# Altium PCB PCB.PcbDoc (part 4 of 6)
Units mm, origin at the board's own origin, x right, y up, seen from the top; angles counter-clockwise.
Board outline 101.6 x 101.61 mm, 4 copper layers (Top Layer, GND, POWER, Bottom Layer), stack 1.371 mm thick; 506 components, 346 nets, 1798 pads, 1471 vias.
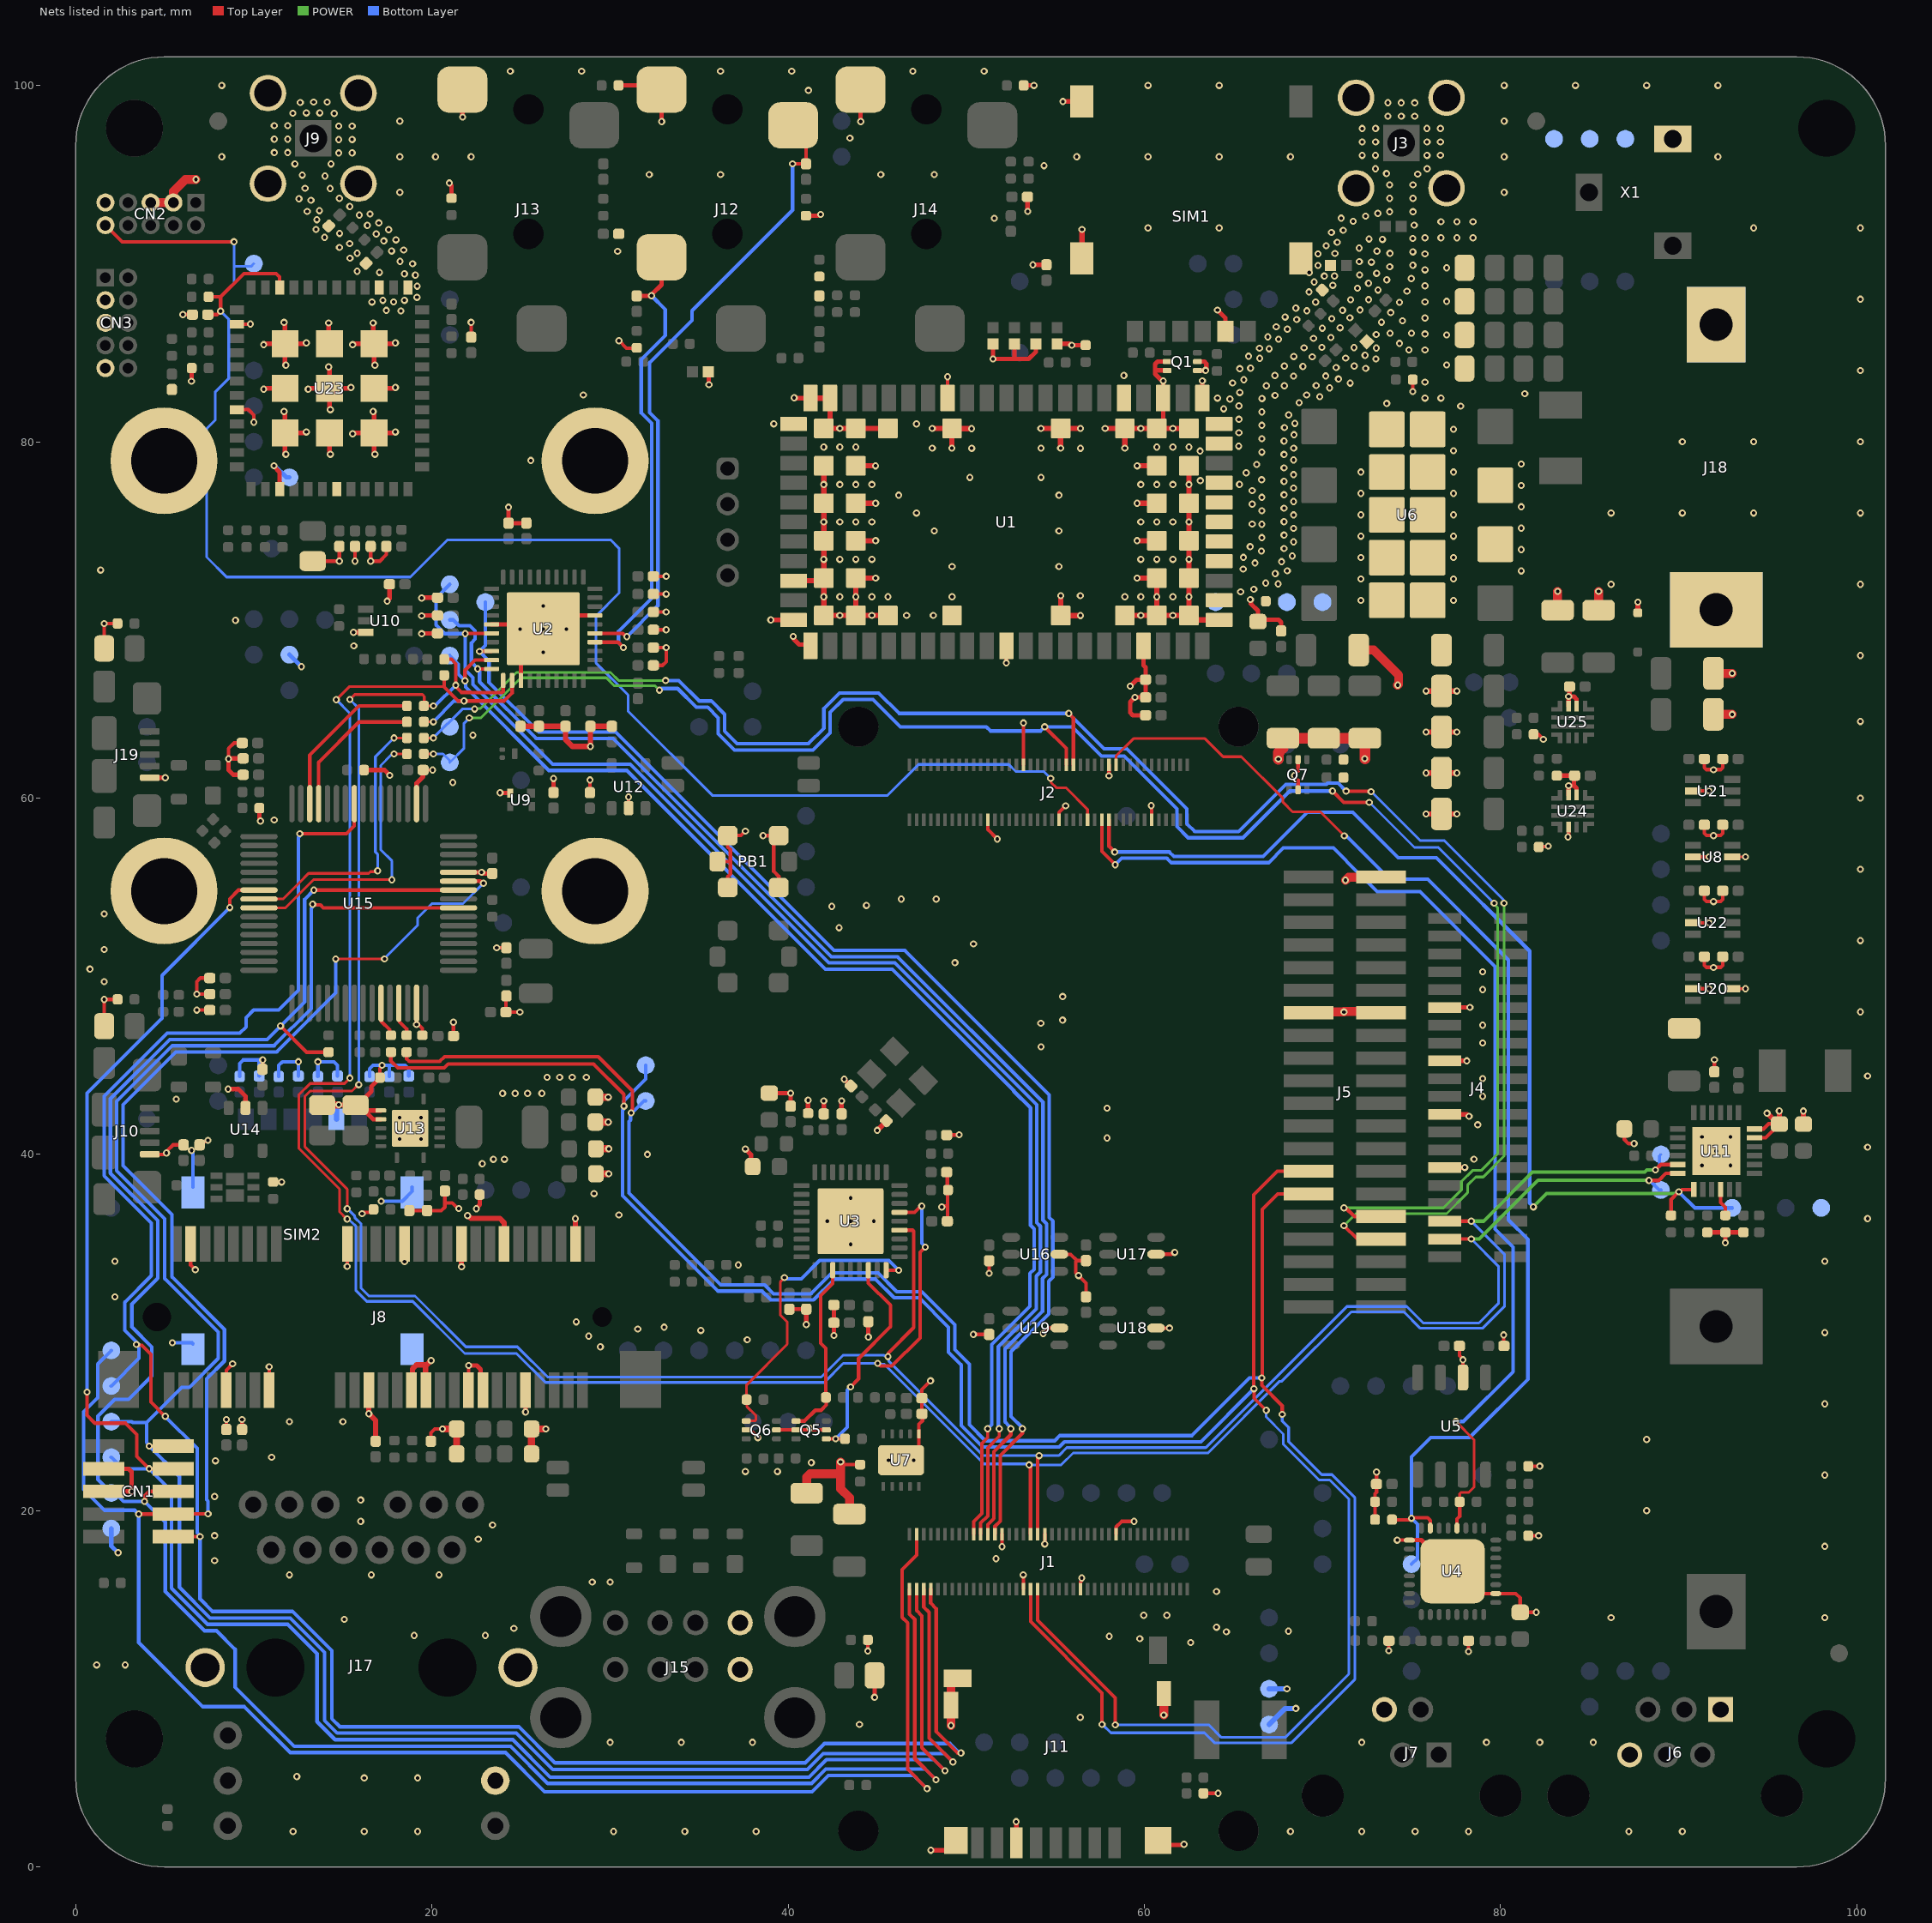
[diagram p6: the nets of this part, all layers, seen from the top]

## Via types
v1: diameter 0.4, hole 0.2, Top Layer to Bottom Layer, tented both sides, 1471 vias

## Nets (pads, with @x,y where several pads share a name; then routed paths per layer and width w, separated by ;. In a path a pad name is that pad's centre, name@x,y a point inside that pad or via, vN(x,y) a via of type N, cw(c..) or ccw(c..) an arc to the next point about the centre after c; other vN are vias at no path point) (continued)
FD_TX_TERM_1: J2.56 R46.1 U4.12 | length 62.1
  Top Layer w0.15: v1(77.479,25.01) 78.5,23.989 78.5,21.315 78.219,21.034 77.788,21.034 77.7,20.946 R46.1@77.7,20.5
  Top Layer w0.2: J2.56@57.61,58.785 57.61,57.009 v1(58.36,56.259) ; U4.12@77.55,19.025 77.55,19.529 77.7,19.679 R46.1@77.7,20.5
  Bottom Layer w0.2: v1(58.36,56.259) 58.726,56.625 61.258,56.625 61.509,56.374 66.974,56.374 67.8,57.2 70.611,57.2 72.09,55.721 73.061,54.751 75.478,54.751 79.69,50.539 79.69,35.805 80.7,34.795 80.7,27.8 77.91,25.01 v1(77.479,25.01)
GND: BAT_GND.X C1.1 C2.1 C3.1 C4.1 C5.1 C6.1 C7.2 C10.1 C11.1 C12.1 C13.1 C14.1 C15.1 C16.1 C17.1 C18.1 C19.1 C20.2 C21.2 C24.1 C25.1 C26.1 C27.1 C28.1 C29.1 C30.1 C32.2 C33.2 C34.1 C35.1 C36.1 C37.1 C39.1 C40.2 C43.1 C44.1 C45.2 C46.2 C48.2 C49.2 C50.2 C51.1 C52.2 C55.2 C56.2 C57.1 C58.2 C59.1 C60.1 C61.1 C62.1 C63.2 C64.1 C65.1 C66.1 C67.1 C68.1 C69.1 C70.1 C71.1 C72.1 C73.1 C74.1 C75.1 C76.1 C77.1 C78.1 C79.1 C80.1 C81.2 C82.1 C83.1 C85.1 C86.2 C87.1 C88.2 C89.1 C90.1 C91.1 C92.1 C94.1 C95.1 C96.1 C97.2 C98.1 C99.1 C100.1 C101.1 C102.1 C103.1 C104.1 C105.1 C106.1 C107.2 C108.1 C109.1 C110.1 C111.1 C112.2 C113.2 C114.2 C115.2 C117.1 C121.1 C122.1 C123.1 C124.1 C125.1 C126.1 C127.2 C129.1 C130.1 C131.1 C132.1 C133.1 C134.1 C135.1 C136.1 C137.1 C138.1 C139.1 C140.1 C141.1 C142.1 C143.1 C144.1 C145.1 C146.1 C147.1 C148.1 C149.1 C150.1 C151.1 C152.1 C153.1 C154.1 C155.1 C156.1 C157.1 C158.1 CN1.3 CN1.5 CN2.3 CN2.5 CN2.9 CN3.3 CN3.5 CN3.9 D1.A D2.A D3.A D4.A D9.A D10.1 D12.A D13.A D14.A D15.A D16.A DBG_GND.X GND_3V3_1.X GND_3V3_2.X GND_3V8_1.X GND_3V8_2.X GND_3V8_3.X H1.1 H2.1 H3.1 H4.1 J1.22 J1.31 J1.42 J1.47 J1.54 J2.24 J2.33 J2.44 J2.57 J2.70 J3.2 J3.3 J3.4 J3.5 J4.6 J4.9 J4.12 J4.15 J5.2 J5.13 J5.14 J6.1 J6.6 J7.4 J8.4 J8.9 J8.15 J8.18 J8.21 J8.26 J8.27 J8.29 J8.34 J8.35 J8.37 J8.40 J8.43 J8.50 J9.2 J9.3 J9.4 J9.5 J10.5 J11.6 J11.CD2 J11.SH1 J11.SH2 J11.SH3 J11.SH4 J12.1 J13.1 J14.1 J15.4 J15.8 J17.13 J17.SH1 J17.SH2 J18.1 J18.2 J19.5 JTAG_GND.X L1.1 LoRa_GND.X PB1.5 PB1.PAD PWR_GND1.X PWR_GND2.X PWR_GND3.X Q1.2 Q1.3 Q1.4 Q1.5 Q5.2 Q5.5 Q6.2 Q6.5 Q7.2 Q7.5 R3.1 R7.1 R17.1 R18.2 R24.1 R25.1 R26.1 R27.1 R28.1 R29.1 R49.2 R50.1 R52.1 R53.2 R55.2 R58.2 R59.1 R66.1 R67.1 R72.2 R74.1 R75.1 R77.1 R78.1 R79.1 R82.1 R84.1 R85.1 R87.2 R89.2 R117.2 R118.1 R121.1 R122.1 R124.1 R126.2 SIM1.C5 SIM1.G1 SIM1.G2 SIM1.G4 SIM2.C5 SIM2.G1 SIM2.G2 SIM2.G3 SIM2.G4 U1.1 U1.3 U1.5 U1.14 U1.20 U1.21 U1.22 U1.30 U1.32 U1.33 U1.43 U1.50 U1.54 U1.55 U1.57 U1.58 U1.59 U1.60 U1.61 U1.63 U1.64 U1.65 U1.66 U1.67 U1.68 U1.69 U1.70 U1.71 U1.72 U1.73 U1.74 U1.75 U1.76 U1.77 U1.78 U1.79 U1.80 U1.81 U1.82 U1.83 U1.84 U1.85 U1.86 U1.87 U1.88 U1.89 U1.90 U1.91 U1.92 U1.93 U1.94 U1.95 U1.96 U2.3 U2.17 U2.35 U2.41 U3.37 U4.2 U4.17 U4.33 U5.2 U6.GND U7.1 U7.11 U8.2 U8.5 U9.2 U10.3 U11.17 U11.18 U11.EXP U12.2 U13.2 U13.3 U13.15 U14.2 U15.12 U15.18 U15.63 U16.2 U17.2 U18.2 U19.2 U20.2 U20.5 U21.2 U22.2 U23.3 U23.7 U23.25 U23.27 U23.38 U23.44 U23.49 U23.50 U23.51 U23.52 U23.53 U23.54 U23.55 U23.56 U23.57 U24.2 U24.8 U24.9 U25.8 U25.9 X1.2 | length 448.4
  Top Layer w0.15: C99.1@19.505,61.575 v1@20.039,61.575 ; U20.5@93,49.3 v1(93.75,49.3) ; U8.5@93,56.7 v1(93.75,56.7)
  Top Layer w0.2: C157.1@1.6,47.2 v1(1.6,48.7) R84.1@2.35,48.7 ; C158.1@1.6,68.4 v1(1.6,69.8) R85.1@2.35,69.8 ; J10.5@4.16,40.01 4.169,40.001 4.962,40.001 5.043,40.083 v1(5.097,40.083) ; v1@5.135,40.06 5.135,40.205 5.465,40.535 C117.1@6.055,40.535 ; v1(6.014,87.138) C60.1@6.549,87.138 ; J8.4@6.457,34.977 6.453,34.973 6.453,33.791 6.713,33.531 v1(6.713,33.528) ; v1(6.8,48.1) C101.1@7.53,48.1 ; C96.1@6.955,40.535 7.139,40.719 7.296,40.719 7.371,40.794 v1(7.425,40.794) ; C109.1@7.53,49 v1(6.8,49) 6.8,49.7 7,49.9 C108.1@7.53,49.9 ; J8.9@8.457,26.777 8.457,27.885 8.809,28.237 v1(8.809,28.246) ; C20.2@8.459,24.558 v1(8.459,25.121) ; v1(8.581,62.203) 8.581,62.782 8.893,63.093 C110.1@9.35,63.093 ; U23.44@9.05,81.8 9.7,81.8 10,81.5 v1(10,81.1) ; U23.38@9.05,86.6 v1@9.8,86.6 ; C52.2@9.339,24.558 v1(9.339,25.121) ; C97.2@10.485,44.775 10.493,44.782 10.493,45.293 v1(10.5,45.3) ; J8.15@10.857,26.777 10.862,26.782 v1(10.862,28.082) ; R89.2@11.085,38.455 11.089,38.451 11.554,38.451 v1(11.557,38.447) ; C12.1@13.3,73.3 v1(14.8,73.3) C13.1@14.8,74.13 ; v1(15.241,33.71) 15.241,34.961 J8.18@15.257,34.977 ; v1(15.68,73.3) C14.1@15.68,74.13 ; v1(16.075,36.675) 16.129,36.675 16.204,36.75 16.555,36.75 R67.1@16.72,36.915 ; C15.1@16.56,74.13 v1(16.56,73.3) 17.075,73.3 17.44,73.665 C11.1@17.44,74.13 ; R66.1@17.057,44.338 R66.1@17.08,44.315 17.08,44.826 17.2,44.946 v1(17.2,45) ; C82.1@18.73,36.845 C34.1@19.73,36.845 20.525,36.845 20.727,37.047 20.727,37.278 ; v1(19.137,47.293) 19.143,47.293 19.211,47.361 19.139,47.433 U15.63@19.139,48.488 ; v1@19.239,47.295 19.459,47.075 R82.1@19.459,46.688 ; C21.2@19.941,23.9 19.941,24.365 20.166,24.59 v1(20.591,24.59) ; C127.2@20.73,37.945 20.727,37.942 20.727,37.278 ; C102.1@21.209,46.648 v1(21.209,47.418) ; v1(21.509,36.96) 21.454,36.96 21.136,37.278 20.727,37.278 ; J8.35@22.057,26.777 v1(22.057,28.156) ; C39.1@22.2,85.87 v1(22.2,86.7) ; v1(23.633,51.593) C112.2@24.178,51.593 ; C107.2@24.178,48.893 24.153,48.868 C98.1@24.153,47.988 v1(24.94,47.988) ; U2.41@25.049,70.69 25.989,69.75 26.239,69.5 U2.41@26.25,69.5 ; U2.41@27.451,68.288 27.451,68.299 U2.41@26.25,69.5 ; U2.41@27.451,70.69 27.44,70.69 27,70.25 U2.41@26.25,69.5 ; C88.2@28.87,60.303 v1(28.87,61.018) ; v1(30.5,85.675) 30.925,85.25 31.475,85.25 R27.1@31.5,85.275 ; v1(31.035,60.063) 31.037,60.061 31.037,59.44 U12.2@31.039,59.438 ; C24.1@32.435,67.45 32.945,67.45 33.15,67.655 v1(33.15,68.45) C27.1@32.435,68.45 ; C26.1@32.435,69.45 v1(33.15,69.45) ; C48.2@32.435,70.45 v1(33.15,70.45) ; C49.2@32.435,71.45 v1(33.15,71.45) ; C51.1@32.435,72.45 v1(33.15,72.45) ; PB1.5@36.024,56.438 36.745,56.438 36.759,56.423 ; PB1.PAD@36.605,54.978 36.605,55.582 36.759,55.736 36.759,56.423 ; v1(37.6,58.15) 37.348,57.898 PB1.PAD@36.605,57.898 36.605,57.264 36.759,57.11 36.759,56.423 ; Q6.2@37.641,24.538 37.691,24.488 37.912,24.488 v1(38.3,24.1) ; v1@38.583,57.898 v1(38.591,57.89) PB1.PAD@39.466,57.89 ; Q6.5@39.341,24.538 40.439,24.538 41.083,24.538 41.17,24.624 v1(41.224,24.624) 41.278,24.624 41.364,24.538 Q5.5@42.139,24.538 ; PB1.PAD@39.473,54.978 39.473,55.607 39.191,55.89 39.191,57.615 PB1.PAD@39.466,57.89 ; PB1.PAD@39.473,57.898 PB1.PAD@39.466,57.89 ; C73.1@40.068,31.315 C74.1@41.017,31.315 ; v1(42.939,22.738) 42.948,22.738 43.098,22.588 R58.2@44.039,22.588 R58.2@44.039,22.588 ; v1(44.475,12.125) R59.1@44.475,12.75 ; v1(47.039,22.838) 47.339,23.138 U7.1@47.339,24.313 47.339,24.848 47.539,25.048 47.539,25.408 C94.1@47.509,25.438 C95.1@47.509,26.318 47.509,26.809 v1(47.991,27.29) ; v1(48.625,37.05) 48.675,37.1 48.955,37.1 ; C89.1@48.897,39.002 48.936,38.962 48.936,37.999 48.955,37.98 48.955,37.1 ; C75.1@48.897,41.087 48.903,41.093 49.593,41.093 v1(49.6,41.1) ; U1.14@48.95,82.45 v1(48.95,83.65) ; C70.1@48.955,36.27 48.955,37.1 ; U1.81@49.194,80.744 U1.81@49.2,80.75 ; v1(50.4,29.9) 50.401,29.899 C63.2@51.283,29.898 C63.2@51.283,29.898 ; J2.24@51.21,58.785 51.21,58.476 51.21,58.232 v1(51.741,57.701) ; v1(51.283,33.325) C113.2@51.283,34.034 ; v1(52.01,17.98) J1.54@52.01,18.685 ; v1(53.2,16.4) 53.21,16.39 J1.47@53.21,15.605 ; v1(53.207,64.219) 53.207,63.504 53.21,63.501 J2.33@53.21,61.865 ; v1(54.319,29.938) 54.636,30.255 U19.2@55.223,30.255 ; v1(54.406,18.131) 54.41,18.134 J1.42@54.41,18.685 ; J2.44@55.21,58.785 55.21,59.195 v1(55.579,59.565) ; U16.2@55.223,34.392 55.859,34.392 56.213,34.038 ; U1.79@55.297,80.747 U1.79@55.3,80.75 U1.79@55.303,80.753 ; J1.31@56.41,15.605 56.41,16.01 56.482,16.082 v1(56.482,16.221) ; C114.2@56.719,32.008 56.719,32.781 v1(56.3,33.2) 56.3,33.211 56.153,33.359 56.153,33.978 56.213,34.038 ; C115.2@56.719,34.038 56.213,34.038 ; v1(58.01,61.249) 58.01,61.556 J2.57@58.01,61.865 ; J1.22@58.41,18.685 58.41,19.089 58.72,19.398 v1(59.42,19.398) ; U1.77@58.9,80.744 U1.77@58.906,80.75 ; J2.70@60.41,58.785 v1@60.41,59.646 ; U18.2@60.659,30.251 v1(61.409,30.251) ; U17.2@60.659,34.395 61.514,34.395 61.619,34.5 v1(61.7,34.5) ; R117.2@63.314,4.138 v1(64.139,4.138) ; Q7.2@68.625,60.46 68.625,61.01 68.425,61.21 v1(68.425,61.26) 68.425,61.314 68.625,61.514 Q7.5@68.625,62.16 ; R118.1@72.95,19.5 R78.1@72.95,20.5 72.95,20.95 73.03,21.03 C59.1@73.03,21.5 v1(73.03,22.17) ; v1(73.721,12.143) 73.726,12.147 73.726,12.696 C55.2@73.73,12.7 ; v1(74.194,18.347) 74.195,18.348 U4.17@74.875,18.35 U4.17@74.875,18.35 ; v1(75.066,82.815) R77.1@75.066,83.49 ; U4.33@77.3,16.6 78.55,15.35 U4.2@79.725,15.35 80.85,15.35 81.1,15.1 C57.1@81.1,14.3 v1(82,14.3) ; C58.2@77.685,29.25 77.685,28.699 77.88,28.504 v1(77.88,28.47) 77.883,28.468 77.883,27.477 U5.2@77.885,27.475 ; v1(78.2,12.1) C56.2@78.2,12.7 ; v1(80.171,29.869) 80.178,29.862 80.178,29.257 C18.1@80.185,29.25 ; R52.1@81.55,18.6 v1(82.13,18.6) ; R49.2@81.55,22.5 v1(82.2,22.5) ; R124.1@81.85,63.58 82.12,63.58 v1(82.4,63.3) ; R121.1@82.138,57.259 82.159,57.28 82.655,57.28 v1(82.675,57.3) ; v1(83.779,57.819) 83.813,57.854 U24.2@83.813,58.37 ; C92.1@86.945,41.43 86.945,40.845 87.184,40.606 v1(87.493,40.606) ; U20.2@90.8,49.3 v1(91.7,49.3) ; U22.2@90.8,53 v1(91.7,53) ; U8.2@90.8,56.7 v1(91.7,56.7) ; U21.2@90.8,60.4 v1(91.7,60.4) ; C134.1@91.435,51.1 91.435,50.617 91.552,50.5 91.946,50.5 v1(91.955,50.491) v1@91.964,50.5 ; C138.1@91.435,54.8 91.435,54.317 91.552,54.2 91.946,54.2 v1(91.955,54.191) v1@91.964,54.2 ; C29.1@91.435,58.5 91.435,58.017 91.552,57.9 91.946,57.9 v1(91.955,57.891) v1@91.964,57.9 ; C136.1@91.435,62.2 91.435,61.717 91.552,61.6 91.946,61.6 v1(91.955,61.591) v1@91.964,61.6 ; v1@91.993,50.529 v1@91.964,50.5 ; v1@91.993,54.229 v1@91.964,54.2 ; v1@91.993,57.929 v1@91.964,57.9 ; v1@91.993,61.629 v1@91.964,61.6 ; C86.2@92,44.73 v1(92,45.317) ; C135.1@92.465,51.1 92.465,50.617 92.348,50.5 v1@91.964,50.5 ; C139.1@92.465,54.8 92.465,54.317 92.348,54.2 v1@91.964,54.2 ; C30.1@92.465,58.5 92.465,58.017 92.348,57.9 v1@91.964,57.9 ; C137.1@92.465,62.2 92.465,61.717 92.348,61.6 v1@91.964,61.6 ; U11.17@94.255,40.93 94.88,40.93 C85.1@95.592,41.642 ; U11.18@94.256,41.429 94.754,41.429 95.041,41.716 C85.1@95.518,41.716 ; C85.1@95.518,41.747 C85.1@95.518,41.716 ; C85.1@95.65,41.7 95.534,41.7 C85.1@95.518,41.716
  Top Layer w0.25: CN1.5@1.578,21.085 v1(3.138,21.085) 3.138,22.185 2.968,22.355 CN1.3@1.578,22.355 ; J19.5@4.16,61.146 v1(5.026,61.146) ; v1(6.5,83.4) 6.507,83.407 6.507,84.131 R18.2@6.514,84.138 ; v1(8.56,43.666) 9.14,43.666 9.535,43.271 U14.2@9.535,42.605 ; C100.1@9.4,61.311 8.847,61.311 8.581,61.576 v1(8.581,62.203) 8.607,62.228 C111.1@9.4,62.227 ; R126.2@10.31,59.438 10.31,58.816 10.372,58.753 v1(10.372,58.713) ; v1(10.55,82.95) 10.6,83 U23.50@11.75,83 ; v1(10.55,85.45) 10.6,85.5 U23.51@11.75,85.5 ; v1(11.131,78.657) 11.131,78.617 11.45,78.298 U23.3@11.45,77.35 ; v1(11.7,81.7) 11.75,81.65 U23.49@11.75,80.5 ; v1(11.7,86.7) 11.75,86.65 U23.51@11.75,85.5 ; v1(11.8,79.3) 11.75,79.35 U23.49@11.75,80.5 ; v1(11.8,84.3) 11.75,84.35 U23.51@11.75,85.5 ; v1(12.95,80.55) 12.9,80.5 U23.49@11.75,80.5 ; v1(12.95,85.55) 12.9,85.5 U23.51@11.75,85.5 ; v1(13.05,82.95) 13.1,83 U23.53@14.25,83 ; v1(14.2,84.2) 14.25,84.15 U23.53@14.25,83 ; v1(14.2,86.675) 14.2,85.55 U23.54@14.25,85.5 ; U23.52@14.25,80.5 14.25,79.35 v1(14.3,79.3) ; v1(14.3,81.8) 14.25,81.85 U23.53@14.25,83 ; v1(14.767,42.787) 14.778,42.776 15.699,42.776 C83.1@15.71,42.765 ; v1(15.45,83.05) 15.4,83 U23.53@14.25,83 ; v1(15.55,80.45) 15.6,80.5 U23.55@16.75,80.5 ; v1(15.55,85.45) 15.6,85.5 U23.57@16.75,85.5 ; v1(15.597,69.305) U10.3@16.285,69.305 ; R79.1@16.185,61.575 17.335,61.575 v1(17.635,61.275) ; v1(16.7,81.7) 16.75,81.65 U23.55@16.75,80.5 ; v1(16.7,86.675) 16.7,85.55 U23.57@16.75,85.5 ; U23.56@16.75,83 17.9,83 v1(17.95,83.05) ; v1(16.8,79.3) 16.75,79.35 U23.55@16.75,80.5 ; v1(16.8,84.3) 16.75,84.35 U23.57@16.75,85.5 ; R66.1@17.08,44.315 17.08,44.292 16.597,43.808 16.597,43.539 15.823,42.765 C83.1@15.71,42.765 ; U13.3@17.13,41.965 16.708,41.965 C83.1@16.208,42.465 ; U13.2@17.13,42.465 C83.1@16.208,42.465 ; v1(17.485,71.055) 17.485,71.073 17.615,71.203 C32.2@17.615,72.005 ; v1(17.95,80.55) 17.9,80.5 U23.55@16.75,80.5 ; v1(17.95,85.55) 17.9,85.5 U23.57@16.75,85.5 ; v1(19.424,69.227) 19.447,69.25 C25.1@20.315,69.25 ; v1(19.424,70.227) 19.447,70.25 C28.1@20.315,70.25 ; v1(19.424,71.227) 19.447,71.25 C43.1@20.315,71.25 ; v1(20.975,94.525) 20.975,94.502 21.1,94.377 R25.1@21.1,93.675 ; J13.1@21.472,100.254 21.712,100.014 J13.1@21.712,99.76 21.712,98.241 v1(21.724,98.229) ; U15.12@21.489,55.838 v1(22.789,55.838) 22.83,55.838 22.9,55.768 C103.1@23.389,55.768 ; v1(22.057,28.156) 22.517,28.156 22.732,27.942 22.732,26.902 J8.37@22.857,26.777 ; v1(22.495,36.951) 22.495,36.992 22.68,37.177 R87.2@22.68,37.745 ; U2.35@23.35,69.75 25.989,69.75 26,69.75 U2.41@26.25,69.5 ; v1(23.825,60.3) 23.838,60.287 24.383,60.287 U9.2@24.395,60.275 ; v1(24.3,76.325) C50.2@24.3,75.435 C46.2@25.3,75.435 ; U2.3@25,66.6 U2.41@25,68.239 ; v1(25.257,25.543) J8.43@25.257,26.777 ; C19.1@26.824,60.293 v1@26.824,61.099 ; U2.41@27,70.25 U2.17@29.15,70.25 ; R24.1@30.475,100 32.648,100 J12.1@32.888,99.76 32.888,97.987 v1(32.9,97.975) ; D12.A@35.525,83.925 35.538,83.913 35.538,83.212 v1(35.55,83.2) ; v1(39.025,70) U1.32@40.3,70 ; v1(40.283,69.072) 40.312,69.044 40.312,68.927 40.621,68.618 41.182,68.618 U1.33@41.25,68.55 ; v1(40.335,82.467) 40.353,82.45 U1.21@41.25,82.45 ; R26.1@41,92.687 41.75,92.687 v1(41.825,92.762) ; v1(41.017,30.45) C74.1@41.017,31.315 ; v1(42.565,29.835) C68.1@42.565,30.55 C69.1@42.565,31.55 ; J14.1@43.824,100 J14.1@44.064,99.76 44.064,97.987 v1(44.076,97.975) ; v1(44.5,29.75) C71.1@44.5,30.615 ; v1(44.85,9.525) C80.1@44.85,10.75 ; v1(48.012,0.943) 49.121,0.943 J11.SH1@49.418,1.24 ; D9.A@51.5,85.5 v1(51.5,84.65) 52.7,84.65 ; v1(52.25,67.589) U1.43@52.25,68.55 ; D3.A@52.7,85.5 52.7,84.65 ; v1(52.803,2.547) 52.811,2.54 52.811,1.369 J11.6@52.818,1.362 ; R28.1@53.225,100 v1(53.8,100) ; C45.2@53.435,93.75 53.435,92.94 v1(53.45,92.925) ; v1(53.735,89.935) C7.2@54.5,89.935 ; D1.A@53.9,85.5 53.9,85.05 53.5,84.65 52.7,84.65 ; D2.A@55.1,85.5 55.8,85.5 55.883,85.417 v1(55.923,85.417) 55.927,85.421 56.696,85.421 R7.1@56.7,85.425 ; v1(55.425,99.1) SIM1.G4@56.495,99.1 ; v1(59.199,66.279) 59.56,66.64 60.055,66.64 C6.1@60.065,66.65 ; v1(59.465,65.652) 59.2,65.387 59.2,64.8 59.35,64.65 C4.1@60.065,64.65 ; v1@59.466,65.651 C5.1@60.064,65.651 ; U1.50@59.95,68.55 59.95,67.45 60.065,67.335 C6.1@60.065,66.65 ; C5.1@60.065,65.65 C6.1@60.065,66.65 ; U1.71@60.7,80.75 61.05,81.1 U1.3@61.05,82.45 61.053,82.453 61.053,83.41 v1(61.057,83.413) 61.016,83.413 60.941,83.488 60.905,83.488 60.593,83.8 60.6,83.806 60.6,84.008 ; J11.SH2@60.768,1.24 62.19,1.24 v1(62.225,1.275) ; Q1.3@61.275,84 61.267,84.008 60.6,84.008 ; Q1.2@61.275,84.5 60.746,84.5 60.6,84.354 60.6,84.008 ; Q1.4@62.975,84 63.476,84 63.476,84.385 63.364,84.498 62.977,84.498 Q1.5@62.975,84.5 ; U1.1@63.25,82.45 63.252,82.452 63.252,83.418 v1(63.255,83.421) ; v1(64.105,87.391) 64.545,86.951 SIM1.C5@64.545,86.2 ; v1(65.948,71.147) 65.977,71.118 65.977,70.909 66.375,70.511 66.375,70.01 67.529,70.01 67.675,69.864 C3.1@67.675,69.38 ; U4.17@74.875,18.35 75.55,18.35 U4.33@77.3,16.6 ; R122.1@83.168,61.259 C65.1@84.153,61.259 84.168,61.259 84.112,61.203 84.112,60.702 ; U24.9@83.813,60.17 83.813,60.698 v1(83.817,60.702) ; U25.9@83.813,65.17 83.813,65.698 v1(83.817,65.702) ; C147.1@83.868,66.259 83.868,65.793 83.817,65.742 v1(83.817,65.702) ; U24.8@84.263,60.17 84.263,60.55 84.112,60.702 ; U25.8@84.263,65.17 84.263,65.55 84.112,65.702 v1(83.817,65.702) ; R74.1@91.6,35.625 R72.2@92.616,35.625 ; v1(92.616,35.043) R72.2@92.616,35.625 ; R75.1@93.632,35.625 R72.2@92.616,35.625 ; C83.1@15.71,42.765 16.01,42.465 C83.1@16.208,42.465 ; U2.41@25,68.239 v1(26.25,69.489) U2.41@26.25,69.5 ; U2.41@25,68.239 25,68.25 U2.41@26.25,69.5 ; v1(83.817,60.702) 83.846,60.73 83.846,60.771 83.817,60.742 v1(83.817,60.702) ; v1(83.817,60.702) 84.112,60.702
  Top Layer w0.26: U15.18@19.139,59.688 19.139,60.838 19.505,61.203 C99.1@19.505,61.575 ; v1(37.6,40.3) 37.906,39.994 37.906,39.414 C77.1@38.006,39.314 ; C76.1@38.939,43.438 v1(40.139,43.438) C72.1@40.139,42.708 ; R55.2@41.12,42.31 v1(41.12,43.04) ; C67.1@42,42.27 v1(42,43) ; C66.1@43,42.27 v1(43,43) ; v1(43.145,44.219) C90.1@43.525,43.84 ; J4.15@76.85,39.25 76.859,39.259 77.977,39.259 v1(77.986,39.268) ; J4.12@76.85,42.25 78.112,42.25 v1(78.225,42.137) ; J4.9@76.85,45.25 v1(78.096,45.25) ; J4.6@76.85,48.25 v1(78.275,48.25)
  Top Layer w0.3: J8.21@16.457,26.777 v1(16.457,25.443) 16.841,25.059 C81.2@16.841,23.9 ; J8.26@18.457,34.977 18.459,34.975 18.459,33.977 v1(18.462,33.975) ; J8.27@18.857,26.777 18.907,26.827 18.907,27.963 19.13,28.186 19.712,28.186 v1(19.954,28.428) ; 19.642,28.085 19.642,26.792 J8.29@19.657,26.777 ; J8.34@21.657,34.977 21.657,33.702 v1(21.666,33.693) ; v1(21.999,36.566) 22.026,36.566 22.18,36.412 23.804,36.412 24.057,36.159 J8.40@24.057,34.977 ; C35.1@24.967,64.03 C36.1@26,64.03 C37.1@27.5,64.03 27.5,63.285 27.885,62.9 v1(28.9,62.9) C33.2@28.9,64.03 C87.1@30.1,64.03 ; J8.50@28.057,34.977 v1(28.057,36.397) ; U1.30@40.3,72.2 41.85,72.2 U1.95@42,72.35 v1(42,71.302) U1.96@42,70.25 v1(42.9,70.25) U1.90@43.8,70.25 ; U1.21@41.25,82.45 U1.20@42.35,82.45 42.348,82.447 42.348,81.097 U1.91@42,80.75 v1(42.9,80.75) U1.85@43.8,80.75 U1.83@45.6,80.75 ; U1.95@42,72.35 v1(42,73.402) U1.94@42,74.45 v1(42,75.502) U1.93@42,76.55 v1(42,77.602) U1.92@42,78.65 ; U1.89@43.8,72.35 v1(43.8,71.302) U1.90@43.8,70.25 ; U1.86@43.8,78.65 v1(44.906,78.65) ; U1.89@43.803,72.347 v1(44.909,72.347) ; U1.88@43.803,74.447 v1(44.909,74.447) ; U1.87@43.803,76.547 v1(44.909,76.547) ; v1(45,41.35) 45.01,41.35 45.5,41.84 C91.1@45.511,41.84 ; U1.84@45.6,70.25 v1(44.7,70.25) U1.90@43.8,70.25 ; v1(48.087,80.75) U1.81@49.194,80.75 ; v1(49.194,79.637) U1.81@49.194,80.744 ; U1.81@49.2,80.744 49.205,80.739 v1(50.301,80.739) ; v1(54.191,80.753) U1.79@55.297,80.753 ; U1.80@55.225,70.325 U1.80@55.297,70.253 ; v1(55.297,79.641) U1.79@55.297,80.747 ; U1.80@55.303,70.247 v1(56.409,70.247) ; U1.80@55.303,70.253 v1(55.303,71.359) ; U1.79@55.303,80.747 v1(56.409,80.747) ; SIM1.G2@56.495,90.3 v1(56.495,91.919) ; v1(57.794,80.75) U1.77@58.9,80.75 58.906,80.75 v1(59.8,80.75) U1.71@60.7,80.75 v1(61.6,80.75) U1.65@62.5,80.75 ; U1.78@58.9,70.25 v1(59.8,70.25) U1.76@60.7,70.25 ; v1(58.9,79.637) U1.77@58.9,80.744 ; v1(59.591,72.347) U1.75@60.697,72.347 ; v1(59.591,74.447) U1.74@60.697,74.447 ; v1(59.591,76.547) U1.73@60.697,76.547 ; v1(59.594,78.65) U1.72@60.7,78.65 ; U1.75@60.7,72.35 v1(60.7,71.302) U1.76@60.7,70.25 ; U1.69@62.5,72.35 v1(62.5,71.302) U1.70@62.5,70.25 ; U1.69@62.5,72.35 v1(62.5,73.402) U1.68@62.5,74.45 v1(62.5,75.502) U1.67@62.5,76.55 v1(62.5,77.602) U1.66@62.5,78.65 ; U1.54@64.2,70 62.75,70 U1.70@62.5,70.25 ; v1(75.81,59.11) C144.1@76.675,59.11 v1(77.54,59.11) ; v1(75.81,61.41) C145.1@76.675,61.41 v1(77.54,61.41) ; v1(75.81,63.71) C146.1@76.675,63.71 v1(77.54,63.71) ; v1(75.81,66.01) C61.1@76.675,66.01 v1(77.54,66.01) ; D10.1@87.7,70.4 v1(87.7,71) ; v1(94.956,42.313) 94.972,42.313 95.518,41.767 C85.1@95.518,41.747 ; v1(95.642,42.437) 95.646,42.433 95.646,41.707 C85.1@95.644,41.706 ; v1(96.998,42.431) 96.999,42.43 96.999,41.701 C140.1@97,41.7 ; U1.76@60.7,70.25 v1(61.6,70.25) U1.70@62.5,70.25
  Top Layer w0.4: C129.1@13.83,42.765 13.834,42.769 14.749,42.769 v1(14.767,42.787) ; v1(20.591,24.59) C130.1@21.391,24.59 C131.1@21.391,23.19 ; C132.1@25.591,23.19 C133.1@25.591,24.59 v1(26.391,24.59) ; C125.1@29.175,41.815 v1(29.896,41.815) ; C126.1@29.175,43.215 v1(29.896,43.215) ; C106.1@29.205,38.915 v1(29.926,38.915) ; C104.1@29.205,40.315 v1(29.926,40.315)
  Top Layer w0.5: CN2.5@4.209,93.428 CN2.3@5.479,93.428 5.479,94.054 6.15,94.725 v1(6.75,94.725) ; C78.1@41.039,20.988 41.039,21.882 41.239,22.081 42.845,22.081 42.939,21.988 ; v1(42.939,22.738) 42.939,21.988 ; C79.1@43.439,19.813 43.439,20.738 42.939,21.238 42.939,21.988 ; v1(49.143,7.943) J11.SH4@49.143,9.087 49.143,10.337 49.393,10.587 J11.CD2@49.516,10.587 ; v1(61.087,8.537) 61.087,9.731 J11.SH3@61.093,9.737 ; J5.13@69.218,47.945 69.268,47.995 v1(71.206,47.995) ; v1@71.206,48.015 73.212,48.015 J5.14@73.282,47.945 ; v1(71.29,55.39) 71.465,55.565 J5.2@73.282,55.565 ; C1.1@71.825,68.31 C1.1@72.025,68.31 72.855,68.31 74.273,66.892 74.273,66.395 v1(74.22,66.342) ; C151.1@83.2,70.55 v1(83.2,71.6) ; C150.1@85.5,70.55 v1(85.5,71.6) ; C148.1@91.95,64.7 v1(93,64.7) ; C149.1@91.95,67 v1(93,67)
  Top Layer w0.6: v1(67.519,62.188) 67.525,62.194 67.525,62.552 67.775,62.802 C143.1@67.775,63.36 C142.1@70.075,63.36 C141.1@72.375,63.36 v1(72.375,62.21)
  Bottom Layer w0.2: v1(5.425,29.425) 6.53,29.425 SIM2.G4@6.59,29.365 ; v1(6.505,40.222) 6.505,40.168 6.59,40.083 SIM2.G2@6.59,38.165 ; C156.1@9.2,44.37 9.2,45.1 9.4,45.3 v1@10.3,45.3 ; D16.A@10.3,44.4 10.3,45.3 ; v1(10.5,45.3) v1@10.3,45.3 ; C155.1@11.4,44.37 11.4,45 11.6,45.2 v1(12.5,45.2) D15.A@12.5,44.4 ; C154.1@13.6,44.37 v1(13.6,45.2) 14.5,45.2 14.7,45 D14.A@14.7,44.4 ; C152.1@16.5,44.37 16.5,44.8 16.7,45 v1(17.2,45) 17.561,45 ; v1(17.146,37.371) 18.34,37.371 18.89,37.921 SIM2.G1@18.89,38.165 ; C153.1@17.6,44.37 17.6,44.961 17.561,45 ; D13.A@18.7,44.4 18.7,44.8 18.5,45 17.561,45 ; v1@19.099,47.255 v1(19.137,47.293)
  Bottom Layer w0.25: JTAG_GND.X@2,19 2,18.023 v1(2.378,17.645) ; v1(11.131,78.657) 11.171,78.657 11.829,78 LoRa_GND.X@12,78 ; DBG_GND.X@12,68.05 v1(12.672,67.378)
  Bottom Layer w0.3: SIM2.C5@14.64,41.965 14.64,42.633 14.767,42.76 v1(14.767,42.787) ; GND_3V3_1.X@67,8 67.9,8.9 v1(68.5,8.9) ; GND_3V3_2.X@67,10 v1(68,10)
  other v1: 12.2,2 16.2,2 19.2,2 30.2,2 34.2,2 38.2,2 68.2,2 72.2,2 75.2,2 78.2,2 87.2,2 90.2,2 16.2,5 19.2,5 12.416,5.075 30,7 34,7 38,7 72.2,7 79.2,7 82.2,7 85.2,7 44,8 56.4,8.4 1.178,11.345 2.778,11.345 62.6,12.6 59.737,12.815 58.027,12.952 19,13 23,13 64.6,13.2 68.088,13.239 24.6,13.4 64.049,13.462 15.079,13.901 86.2,14 98.2,14 59.96,14.127 61.26,14.127 64.049,15.464 29,16 30,16 12,16.4 16.6,16.4 20.4,16.4 7.8,17.2 51.666,17.305 98.2,18 22.6,18.4 7.8,18.6 23.4,19.2 16,19.4 88.2,20 16,20.6 7.8,20.8 98.2,22 37.6,22.2 39.4,22.2 41.3,22.7 7.843,22.802 45.639,22.838 11,23 88.2,24 12,25 15,25 98.2,26 29.457,29.197 37.7,29.6 28.8,29.8 98.2,30 35.093,30.121 31.557,30.197 33.035,30.3 28.1,30.6 2.2,32 37.2,33.8 2.2,34 98.2,34 43.5,34.95 42.2,36.25 43.5,36.25 44.8,36.25 100.6,36.4 30.5,36.6 43.5,37.55 29.1,37.8 91.3,39.38 92.9,39.38 22.825,39.475 23.45,39.725 24.07,39.725 78.501,39.728 32.1,40 92.1,40.18 100.6,40.4 18.18,40.865 19.38,40.865 57.902,40.919 91.3,40.98 92.9,40.98 78.712,41.661 18.18,42.065 19.38,42.065 57.902,42.596 5.646,43.103 78.987,43.254 23.97,43.425 24.67,43.425 25.37,43.425 26.17,43.425 78.987,44.254 26.47,44.325 27.17,44.325 27.87,44.325 28.67,44.325 100.6,44.4 54.194,46.035 78.987,46.254 78.987,47.254 54.185,47.359 55.406,47.535 100.2,48 55.415,48.859 78.987,49.254 1.6,49.7 78.987,50.254 0.8,50.4 49.363,50.763 1.6,51.5 50.404,51.819 100.2,52 42.856,52.723 1.6,53.5 42.448,53.921 44.393,53.975 46.35,54.333 48.31,54.333 100.2,56 11.14,58.773 60.384,59.581 100.2,60 21.165,60.876 26.824,61.1 20.041,61.577 22.3,63.53 100.2,64.3 100.2,68 26.25,68.189 15.615,68.541 24.95,69.489 27.55,69.489 8.972,69.978 46.652,70.25 48.148,70.25 26.25,70.789 72.155,71.1 77.355,71.1 42.9,71.302 44.7,71.302 45.6,71.302 49.2,71.302 58.9,71.302 59.8,71.302 61.6,71.302 56.406,71.363 65.403,71.576 66.144,71.718 67.504,72.02 86.2,72 100.2,72 66.811,72.068 72.155,72.3 77.355,72.3 67.345,72.601 81.155,72.75 68.02,72.759 1.4,72.8 65.544,72.85 49.2,73 55.2,73 66.213,73.198 67.696,73.268 42.9,73.402 43.8,73.402 44.7,73.402 59.8,73.402 60.7,73.402 61.6,73.402 65.561,73.509 72.155,73.5 77.355,73.5 68.298,73.588 66.565,73.865 81.155,73.95 67.839,74.009 65.936,74.112 68.375,74.385 66.591,74.618 72.155,74.7 77.355,74.7 67.84,74.763 48.2,75 55.2,75 68.375,75.14 81.155,75.15 66.591,75.372 66.055,75.377 42.9,75.502 43.8,75.502 44.7,75.502 59.8,75.502 60.7,75.502 61.6,75.502 67.84,75.517 68.375,75.894 72.155,75.9 77.355,75.9 47.2,76 86.2,76 90.2,76 94.2,76 100.2,76 66.591,76.126 67.84,76.271 81.155,76.35 66.055,76.503 68.375,76.648 66.591,76.88 46.2,77 55.2,77 67.84,77.025 72.155,77.1 77.355,77.1 66.055,77.257 68.375,77.402 81.155,77.55 42.9,77.602 43.8,77.602 44.7,77.602 59.8,77.602 60.7,77.602 61.6,77.602 65.337,77.606 67.84,77.779 63.14,77.819 66.58,77.868 50.2,78 54.2,78 68.375,78.156 65.711,78.259 72.155,78.3 77.355,78.3 67.84,78.533 66.303,78.724 81.155,78.75 25.55,78.95 68.375,78.982 67.84,79.287 66.596,79.418 63.127,79.48 77.355,79.5 48.087,79.637 50.303,79.634 54.194,79.637 56.409,79.634 68.383,79.646 42,79.702 42.9,79.702 43.8,79.702 60.7,79.702 61.6,79.702 62.5,79.702 65.297,79.754 90.2,80 94.2,80 100.2,80 67.84,80.041 66.594,80.171 68.395,80.395 65.308,80.507 77.355,80.7 67.862,80.794 66.592,80.923 39.191,81.009 47.2,81 68.449,81.031 65.306,81.26 68.099,81.51 66.59,81.676 64.45,81.85 77.755,82 65.305,82.013 73.605,82.15 68.685,82.197 64.8,82.4 66.601,82.429 64.1,82.45 75.75,82.45 76.65,82.45 69.84,82.535 67.334,82.6 28.5,82.628 69.11,82.627 81.355,82.7 65.355,82.764 70.393,83.02 66.845,83.141 67.856,83.143 69.643,83.16 71.55,83.294 64.95,83.3 75.75,83.35 65.586,83.48 70.897,83.524 68.378,83.686 70.176,83.693 58.85,83.725 67.327,83.719 63.435,84.006 100.2,84 65.35,84.1 65.961,84.133 72.424,84.122 70.765,84.163 68.899,84.229 67.858,84.253 71.777,84.25 76.964,84.314 72.996,84.645 66.473,84.685 71.296,84.697 69.421,84.772 68.389,84.787 65.85,84.8 72.386,84.853 74.85,85.15 75.75,85.15 67.004,85.219 66.461,85.252 68.965,85.272 73.017,85.265 69.961,85.296 71.769,85.283 74.323,85.523 67.535,85.752 69.496,85.806 70.473,85.848 66.932,85.89 76.97,85.997 73.015,86.017 75.75,86.05 73.791,86.09 74.991,86.09 68.027,86.322 69.988,86.375 70.985,86.4 67.4,86.45 9.81,86.61 73.307,86.711 74.491,86.79 68.549,86.865 70.519,86.909 75.75,86.95 71.533,86.962 67.9,87 73.829,87.254 18.254,87.344 69.124,87.35 17.435,87.376 71.124,87.378 72.108,87.398 68.5,87.5 16.634,87.842 69.615,87.837 74.321,87.823 17.85,87.85 75.75,87.85 76.97,87.879 17.244,87.939 18.456,87.939 71.577,87.972 72.591,87.976 100.2,88 19.161,88.108 69.237,88.41 74.741,88.449 73.112,88.519 71.963,88.619 19.168,88.734 75.75,88.75 70.575,88.784 72.581,88.894 69.529,88.969 73.605,89.089 74.984,89.161 70.1,89.3 70.671,89.309 19.067,89.354 72.079,89.362 18.456,89.423 73.036,89.457 17.055,89.506 69.25,89.5 15.801,89.573 75.75,89.65 76.97,89.761 73.772,89.823 69.75,89.9 75.074,89.909 18.913,89.99 72.743,90.081 18.211,90.125 72.064,90.115 15.4,90.302 69.75,90.55 75.75,90.55 15.801,90.584 70.699,90.57 73.783,90.575 75.072,90.661 17.733,90.707 30.423,90.693 73.057,90.706 18.416,90.765 72.062,90.868 14.808,90.909 70.2,91 15.379,91.128 70.822,91.2 17.301,91.276 17.977,91.333 73.364,91.358 72.611,91.383 75.07,91.414 75.75,91.45 76.65,91.45 77.55,91.45 78.45,91.45 13.968,91.475 16.872,91.668 14.818,91.697 70.5,91.75 71.162,91.872 17.57,91.907 13.487,91.92 60.2,92 64.2,92 94.2,92 100.2,92 16.372,92.144 75.147,92.163 17.02,92.284 76.65,92.35 77.55,92.35 78.45,92.35 71.72,92.377 13.541,92.466 51.569,92.544 71.05,92.55 72.417,92.661 15.922,92.727 16.528,92.786 73.102,92.82 73.765,92.913 75.079,92.913 13,92.926 13.686,92.97 15.386,93.206 13.209,93.555 12.535,93.638 14.804,93.663 73.767,93.666 75.077,93.666 18.2,94 80.2,94 14.282,94.219 12.875,94.231 73.769,94.419 75.075,94.419 14.001,94.918 12.721,94.969 32.2,95 36.2,95 45.2,95 48.2,95 75.342,95.022 73.592,95.055 72.974,95.325 75.87,95.325 54.368,95.498 12.303,95.597 14.333,95.595 8.2,96 18.2,96 20.2,96 22.2,96 56.2,96 60.2,96 64.2,96 68.2,96 80.2,96 92.2,96 72.223,96.076 72.976,96.078 75.868,96.078 76.621,96.08 14.768,96.211 15.521,96.213 11.149,96.233 11.902,96.235 72.225,96.829 72.977,96.831 75.867,96.831 76.619,96.833 11.149,96.987 11.902,96.989 14.768,96.965 15.521,96.967 43.468,97.042 72.226,97.582 72.979,97.584 75.865,97.584 76.618,97.586 14.768,97.719 15.521,97.721 11.149,97.741 11.902,97.743 18.2,98 80.2,98 73.669,98.276 74.422,98.274 75.175,98.272 14.516,98.43 12.195,98.438 12.949,98.461 13.703,98.461 12.605,99.047 73.667,99.029 74.42,99.027 75.173,99.025 13.359,99.07 14.113,99.07 41.134,99.725 8.2,100 60.2,100 64.2,100 80.2,100 84.2,100 88.2,100 92.2,100 24.4,100.8 28.4,100.8 36.2,100.8 40.2,100.8 47,100.8 51,100.8
GPIO.3_1: C60.2 CN2.10 J2.52 LORA_RST.X R14.1 U23.34 | length 99.7
  Top Layer w0.15: v1(54.739,61.107) 54.753,61.093 54.753,60.882 55.054,60.581 55.589,60.581 56.81,59.36 J2.52@56.81,58.785
  Top Layer w0.2: CN2.10@1.669,92.158 2.602,91.225 v1(8.887,91.225) ; C60.2@7.419,87.138 7.938,87.138 v1(8.133,87.332) 8.133,88.138 ; R14.1@7.459,88.138 8.133,88.138 ; U23.34@11.45,88.65 11.45,89.256 11.259,89.446 9.442,89.446 8.133,88.138
  Bottom Layer w0.15: v1(8.887,91.225) 8.887,89.89 ; LORA_RST.X@10,90 9.843,89.843 8.935,89.843 8.887,89.89 ; v1(54.739,61.107) 54.356,61.49 52.775,61.49 52.375,61.89 47.319,61.89 45.579,60.15 35.739,60.15 31.016,64.873 31.016,65.782 29.201,67.597 29.201,70.201 30.505,71.505 30.505,74.027 30.044,74.488 20.862,74.488 18.783,72.409 8.466,72.409 7.35,73.525 7.35,80.743 7.841,81.233 7.841,82.81 8.589,83.559 8.589,86.874 8.133,87.33 v1(8.133,87.332) 8.133,88.138 8.887,88.891 8.887,89.89
GPIO.6_1: INT_BQ.X J2.58 R76.2 U11.7 | length 58.1
  Top Layer w0.2: J2.58@58.01,58.785 58.01,57.294 v1(58.331,56.973) ; R76.2@89.568,36.575 89.568,37.468 v1(90,37.9) 90.054,37.9 90.179,38.025 U11.7@90.85,38.025
  POWER w0.2: v1(81.836,37.052) 82.583,37.8 v1@89.846,37.8
  Bottom Layer w0.2: v1(58.331,56.973) 58.332,56.975 61.403,56.975 61.654,56.724 66.668,56.724 69.144,59.2 71.7,59.2 74.249,56.651 76.394,56.651 81.626,51.419 81.626,37.267 81.836,37.057 v1(81.836,37.052) ; v1(90,37.9) 90.9,37 INT_BQ.X@93,37
H/Fn_1: H/Fn.X J2.59 R118.2 U4.15 | length 69.5
  Top Layer w0.15: J2.59@58.41,61.865 58.41,62.363 59.387,63.34 63.399,63.34 64.419,62.319 65.441,62.319 67.778,59.982 67.778,59.77 68.319,59.228 69.875,59.228 v1(71.221,57.882)
  Top Layer w0.2: R118.2@73.9,19.5 73.912,19.488 74.909,19.488 v1(74.998,19.577) 75.021,19.6 75.9,19.6 76.05,19.45 U4.15@76.05,19.025
  Bottom Layer w0.2: v1(71.221,57.882) 71.343,57.882 73.774,55.451 75.901,55.451 80.438,50.913 80.438,36.323 81.532,35.229 81.532,27.377 78.255,24.1 76.076,24.1 74.998,23.023 v1(74.998,19.577) 74.998,19.538 75.049,19.487 75.088,19.487 75.326,19.249 75.326,17.326 H/Fn.X@75,17
HP/LINE_OUTA_4: C22.2 J12.2 U2.15 | length 35.8
  Top Layer w0.2: U2.15@29.15,69.25 30.712,69.25 30.904,69.059 v1(30.945,69.059) ; v1(40.245,95.599) v1(40.245,95.599) 40.999,95.598 C22.2@41,95.597 ; J12.2@40.288,97.76 41,97.048 C22.2@41,95.685
  Bottom Layer w0.2: v1(30.945,69.059) 32.685,70.798 32.685,81.18 32.225,81.639 32.225,84.441 34.6,86.816 34.6,87.358 40.245,93.004 v1(40.245,95.599)
HP/LINE_OUTB_4: C23.2 J12.3 U2.14 | length 26.7
  Top Layer w0.2: U2.14@29.15,68.75 30.452,68.75 30.736,68.466 v1@30.736,68.452 ; v1@32.25,88.193 32.263,88.193 32.317,88.193 v1(32.325,88.2)
  Top Layer w0.25: C23.2@31.5,88.185 32.256,88.185 32.263,88.193 32.296,88.226 32.31,88.226 32.354,88.269 32.354,88.283 32.888,88.817 J12.3@32.888,90.36
  Bottom Layer w0.2: v1@30.736,68.452 30.476,68.712 30.476,69.365 32.335,71.224 32.335,81.035 31.752,81.617 31.752,84.618 33.1,85.966 33.1,87.425 v1(32.325,88.2)
  other v1: 30.75,68.452
HUB_EN1_8: Q5.1 R114.1 U3.12 | length 10
  Top Layer w0.2: Q5.1@40.439,25.038 40.921,25.038 41.521,25.638 41.839,25.638 42.139,25.938 42.139,26.338 R114.1@42.119,26.358 42.119,29.119 41.831,29.407 41.831,32.079 42.5,32.748 U3.12@42.5,33.5
HUB_EN2_8: Q5.4 R115.1 U3.16 | length 12.3
  Top Layer w0.2: Q5.4@42.139,24.038 v1(42.664,24.038) R115.1@43.189,24.038 ; v1(43.5,26.951) 43.953,27.404 43.953,28.546 45.739,30.333 45.739,31.538 44.5,32.777 U3.16@44.5,33.5
  Bottom Layer w0.2: v1(42.664,24.038) 43.318,24.692 43.318,26.769 v1(43.5,26.951)
HUB_EN3_8: Q6.1 R113.1 U3.18 | length 17.8
  Top Layer w0.15: Q6.1@37.641,25.038 38.132,25.038 38.191,25.097 38.191,25.347 37.679,25.859 37.679,26.225 R113.1@37.666,26.238 37.666,27.065 39.949,29.348 39.949,30.6 39.553,30.995 39.553,32.83 39.791,33.068 v1(39.791,33.09)
  Top Layer w0.2: U3.18@45.5,33.5 v1(46.202,33.5)
  Bottom Layer w0.2: v1(39.791,33.09) 39.845,33.09 39.915,33.02 40.734,33.02 41.764,34.05 45.652,34.05 v1(46.202,33.5)
I2C0.SCL_1: HUB_SCL.X J1.46 J4.18 R34.2 R105.2 U2.2 U3.24 U11.5 | length 162.8
  Top Layer w0.15: v1(14.628,65.526) 15.354,66.252 20.691,66.252 ; v1(15.24,36.372) 15.217,36.372 14.815,36.774 14.815,38.054 12.525,40.344 12.525,43.346 13.16,43.982 15.089,43.982 v1(15.395,44.287) ; R105.2@19.545,64.275 v1@20.079,64.275
  Top Layer w0.2: R34.2@20.691,66.89 20.691,66.252 20.691,66.229 21.466,65.454 v1(21.801,65.454) 24.054,65.454 24.5,65.899 U2.2@24.5,66.6 ; v1(45.026,28.272) 45.033,28.272 45.184,28.12 45.826,28.12 47.4,29.694 47.4,34.5 v1(47.7,34.8) ; U3.24@46.25,36.75 47.088,36.75 47.429,37.092 v1(47.499,37.092) ; v1(53.527,22.572) 53.61,22.49 J1.46@53.61,18.685 ; J4.18@76.85,36.25 v1(78.35,36.25) ; v1(88.688,39.126) 88.992,39.43 U11.5@89.945,39.43
  POWER w0.2: v1(78.35,36.25) 79.031,36.25 81.781,39 88.088,39 88.214,39.126 v1(88.688,39.126)
  Bottom Layer w0.15: v1(14.628,65.526) 15.395,64.76 v1(15.395,44.287) ; v1(15.24,36.372) 15.308,36.372 15.51,36.17 15.533,36.17 15.721,35.981 15.721,32.371 16.342,31.75 18.917,31.75 21.842,28.825 24.751,28.825 26.376,27.2 42.021,27.2 43.093,28.272 v1(45.026,28.272) 45.072,28.226 45.395,28.226 50.996,22.625 53.475,22.625 v1(53.527,22.572) 55.328,22.572 55.999,23.244 63.572,23.244 67.594,27.266 67.72,27.266 71.617,31.162 74.569,31.162 75.493,30.237 78.976,30.237 80.226,31.488 80.226,34.374 v1(78.35,36.25) ; v1(88.688,39.126) 88.92,39.357 88.92,39.92 HUB_SCL.X@89,40
  Bottom Layer w0.2: v1(20.081,64.277) 20.081,64.286 21.249,65.454 v1(21.801,65.454) ; v1(47.499,37.092) 47.499,35.017 47.7,34.816 v1(47.7,34.8)
I2C0.SDA_1: HUB_SDA.X J1.44 J4.19 R35.2 R106.2 U2.1 U3.22 U11.6 | length 155.7
  Top Layer w0.15: v1(15.24,36.95) 15.24,38.053 12.87,40.423 12.87,43.267 13.16,43.557 15.514,43.557 15.869,43.911 v1(15.892,43.911) ; v1(15.396,65.535) 15.671,65.81 19.464,65.81 19.567,65.708 19.567,65.197 R106.2@19.545,65.175 v1@20.079,65.175
  Top Layer w0.2: R35.2@20.691,67.79 21.091,67.79 21.339,67.541 v1(21.339,66.335) 21.378,66.297 21.378,66.203 21.645,65.935 22.195,65.935 22.209,65.922 23.941,65.922 24,65.98 U2.1@24,66.6 ; v1(45.599,28.651) 45.618,28.671 45.618,28.855 47.044,30.281 47.044,35.691 46.985,35.75 U3.22@46.25,35.75 ; J1.44@54.01,18.685 54.01,22.955 54.09,23.035 v1(54.09,23.089) ; J4.19@76.85,35.25 v1(78.35,35.25) ; v1(88.324,38.538) 88.886,38.538 89.278,38.93 U11.6@89.945,38.93
  POWER w0.2: v1(78.35,35.25) 78.798,35.25 82.105,38.557 88.305,38.557 v1(88.324,38.538)
  Bottom Layer w0.15: v1(15.24,36.95) 15.263,36.95 15.65,36.563 15.65,36.499 15.677,36.472 15.677,36.452 16.021,36.108 16.021,32.495 16.466,32.05 19.05,32.05 21.9,29.2 24.8,29.2 26.5,27.5 41.854,27.5 43.076,28.722 45.386,28.722 45.409,28.699 45.533,28.699 v1@45.59,28.642 ; v1(15.396,65.535) 15.893,65.038 v1(15.892,43.911) ; v1(45.599,28.651) 45.646,28.603 45.646,28.399 50.956,23.089 v1(54.09,23.089) 55.189,23.089 55.644,23.544 63.448,23.544 71.367,31.462 74.733,31.462 75.658,30.537 78.781,30.537 79.876,31.633 79.876,33.724 v1(78.35,35.25)
  Bottom Layer w0.2: v1(20.081,65.177) 20.119,65.215 20.216,65.215 21.336,66.335 v1(21.339,66.335) ; v1(88.324,38.538) 88.378,38.538 88.916,38 HUB_SDA.X@89,38
I2C1.SCL_1: I2C1_SCL.X J1.45 J5.29 R91.2 | length 124.7
  Top Layer w0.19: J1.45@53.61,15.605 53.61,13.771 57.62,9.761 v1(57.62,7.999)
  Top Layer w0.2: R91.2@18.574,45.733 18.579,45.729 18.579,45.363 18.729,45.213 20.433,45.213 20.705,45.485 29.342,45.485 31.259,43.569 31.259,42.552 31.224,42.517 31.224,42.373 v1(31.185,42.334) ; v1(67.738,25.404) 67.738,25.89 66.588,27.04 v1(66.588,27.453) 66.617,27.482 66.617,36.917 67.485,37.785 J5.29@69.218,37.785
  Bottom Layer w0.15: v1(57.62,7.999) 57.652,7.999 58.119,7.532 63.368,7.532 63.925,6.975 68.261,6.975 71.813,10.527 71.813,20.741 70.529,22.025 69.957,22.025 68.1,23.882 68.1,24.672 67.738,25.033 v1(67.738,25.404)
  Bottom Layer w0.2: I2C1_SCL.X@32,43 31.905,43 31.239,42.334 v1(31.185,42.334) 31.147,42.296 31.147,41.933 31.055,41.841 31.055,37.826 36.206,32.675 38.682,32.675 39.178,32.179 41.279,32.179 42.45,33.35 45.045,33.35 46.095,32.3 47.495,32.3 49.35,30.445 49.35,29.05 50.176,28.224 50.176,24.824 51.071,23.929 54.959,23.929 55.249,24.219 62.662,24.219 65.896,27.453 v1(66.588,27.453)
I2C1.SDA_1: I2C1_SDA.X J1.43 J5.27 R90.2 | length 126.9
  Top Layer w0.19: J1.43@54.01,15.605 54.01,13.852 58.366,9.496 v1(58.366,7.977) ; 66.139,37.739 66.139,26.856 v1(66.149,26.846) 66.149,26.328 v1(66.839,25.638)
  Top Layer w0.2: R90.2@17.694,45.733 17.694,45.255 17.689,45.25 18.085,44.855 18.326,44.855 18.328,44.853 19.498,44.853 19.5,44.855 20.687,44.855 20.914,45.082 29.075,45.082 30.779,43.377 v1(30.779,42.709) ; 66.139,37.739 67.455,39.055 J5.27@69.218,39.055
  Bottom Layer w0.15: v1(58.366,7.977) 63.623,7.977 64.325,7.275 67.912,7.275 71.477,10.84 71.477,20.653 70.405,21.725 69.803,21.725 67.8,23.728 67.8,24.3 66.839,25.261 v1(66.839,25.638)
  Bottom Layer w0.2: I2C1_SDA.X@32,45 32,44.232 30.782,43.014 30.782,42.712 30.741,42.671 30.741,42.527 30.705,42.49 30.705,37.681 36.061,32.325 38.537,32.325 39.033,31.829 41.424,31.829 42.595,33 44.9,33 45.95,31.95 47.35,31.95 49,30.3 49,28.905 49.72,28.185 49.72,24.785 50.926,23.579 55.219,23.579 55.509,23.869 63.172,23.869 v1(66.149,26.846)
I2C1_SCL_3: R91.1 U15.61 | length 2
  Top Layer w0.2: U15.61@18.139,48.488 18.158,48.468 18.158,47.467 18.579,47.046 R91.1@18.579,46.688
I2C1_SDA_3: R90.1 U15.59 | length 2
  Top Layer w0.2: U15.59@17.139,48.488 17.158,48.468 17.158,47.469 17.623,47.004 17.623,46.764 R90.1@17.699,46.688
I2C2.SCL_1: I2C2_SCL.X J2.47 J5.34 R110.1 | length 104.4
  Top Layer w0.15: R110.1@19.545,63.375 20.079,63.375 v1(20.081,63.377)
  Top Layer w0.2: v1(55.754,64.756) 56.01,64.5 J2.47@56.01,61.865 ; v1(71.2,36) 71.955,35.245 J5.34@73.282,35.245 ; v1(71.32,60.392) 71.336,60.376 72.709,60.376 v1(72.725,60.36)
  POWER w0.15: v1(22.4,65) 22.428,65.028 22.729,65.028 24.751,67.05 30.029,67.05 30.478,66.6 v1(33.124,66.6) ; v1(71.2,36) 71.876,36.676 76.967,36.676 78.139,37.849 78.139,38.269 78.604,38.733 79.024,38.733 80.187,39.896 v1(80.187,54.101)
  Bottom Layer w0.15: v1(20.081,63.377) 21.704,65 v1(22.4,65) ; v1(72.725,60.36) 72.746,60.36 75.49,57.616 76.839,57.616 80.139,54.316 80.139,54.148 v1(80.187,54.101)
  Bottom Layer w0.2: v1(33.124,66.6) 33.853,66.6 35,65.454 35.675,65.454 36.424,64.705 36.424,63.763 37.137,63.05 41.134,63.05 42.006,63.922 42.006,65.022 42.884,65.9 45.078,65.9 46.222,64.756 v1(55.754,64.756) 55.754,64.742 57.728,62.768 59.016,62.768 62.389,59.395 62.389,58.563 62.828,58.124 65.284,58.124 67.933,60.773 70.218,60.773 70.29,60.845 70.872,60.845 71.32,60.397 v1(71.32,60.392)
I2C2.SDA_1: I2C2_SDA.X J2.45 J5.32 R109.1 | length 104.2
  Top Layer w0.15: R109.1@19.545,62.475 v1@20.079,62.475
  Top Layer w0.2: v1(54.4,64) 55.61,62.79 J2.45@55.61,61.865 ; v1(70.56,60.395) 71.195,59.76 v1(72.625,59.76) ; v1(71.2,37) 71.299,37 71.784,36.515 J5.32@73.282,36.515
  POWER w0.15: v1(22.1,64.5) 22.749,64.5 24.999,66.75 29.795,66.75 30.244,66.3 32.532,66.3 v1(32.775,66.057) ; v1(71.2,37) 76.79,37 77.801,38.011 77.801,38.481 78.42,39.1 78.9,39.1 79.835,40.035 79.835,53.852 79.634,54.052 v1(79.634,54.1)
  Bottom Layer w0.15: v1(20.081,62.477) 20.621,62.477 21,62.099 I2C2_SDA.X@21,62 21.8,62.8 21.8,64.2 v1(22.1,64.5) ; v1(72.625,59.76) 72.634,59.76 75.164,57.23 76.504,57.23 v1(79.634,54.1)
  Bottom Layer w0.2: v1(32.775,66.057) 32.829,66.057 32.922,66.15 33.796,66.15 34.85,65.097 35.483,65.097 36.074,64.506 36.074,63.618 36.992,62.7 41.397,62.7 42.356,63.659 42.356,64.808 43.088,65.541 44.757,65.541 46.297,64 51.126,64 51.357,63.769 54.169,63.769 v1(54.4,64) 55.963,64 57.597,62.366 58.864,62.366 61.826,59.404 61.826,58.406 62.458,57.774 65.534,57.774 68.155,60.395 v1(70.56,60.395)
I2C2_SCL_3: R105.1 U15.29 | length 8.2
  Top Layer w0.2: U15.29@13.639,59.688 13.639,62.006 15.908,64.275 R105.1@18.595,64.275
I2C2_SDA_3: R106.1 U15.30 | length 9.3
  Top Layer w0.2: U15.30@13.139,59.688 13.139,62.408 15.906,65.175 R106.1@18.595,65.175
I2C3_SCL_3: R109.2 U15.41 | length 16.5
  Top Layer w0.15: U15.41@10.289,53.838 11.769,53.838 13.354,55.422 17.74,55.422 v1(17.751,55.411) ; v1(17.87,62.475) R109.2@18.595,62.475
  Bottom Layer w0.15: v1(17.751,55.411) 17.759,55.419 17.759,56.466 17.125,57.1 17.125,61.83 17.722,62.427 17.822,62.427 v1(17.87,62.475)
I2C3_SDA_3: R110.2 U15.40 | length 16
  Top Layer w0.15: U15.40@10.289,54.338 11.638,54.338 12.552,55.252 13.074,55.774 16.45,55.774 16.545,55.87 16.902,55.87 v1(16.95,55.917) ; v1(17.87,63.375) R110.2@18.595,63.375
  Bottom Layer w0.15: v1(16.95,55.917) 16.95,56.85 16.825,56.975 16.825,62.33 v1(17.87,63.375)
I2S.CK_1: I2S_CK.X J1.56 U2.38 | length 73.2
  Top Layer w0.2: v1(22.673,68.235) 22.681,68.243 23.343,68.243 U2.38@23.35,68.25 ; J1.56@51.61,18.685 51.61,19.129 51.903,19.422 51.903,23.103 53.15,24.35 v1(53.15,24.6)
  Bottom Layer w0.2: I2S_CK.X@23,71 23,68.562 v1(22.673,68.235) 23.2,67.708 23.2,66.5 26,63.7 30.321,63.7 42.571,51.45 46.55,51.45 54.655,43.345 54.655,36.46 54.861,36.255 54.861,33.116 54.627,32.883 54.627,31.042 52.518,28.933 52.518,25.29 53.15,24.657 v1(53.15,24.6)
I2S.SDI_1: I2S_SDI.X J1.60 U2.36 | length 76
  Top Layer w0.19: J1.60@50.81,18.685 50.81,19.312 51.208,19.71 51.208,23.539 51.85,24.181 v1(51.85,24.6)
  Top Layer w0.2: v1(21.869,69.232) 21.878,69.241 23.341,69.241 U2.36@23.35,69.25
  Bottom Layer w0.2: I2S_SDI.X@21,72 20.224,71.224 20.224,69.715 20.707,69.232 v1(21.869,69.232) 21.869,67.202 22.305,66.766 22.305,66.371 26.777,61.9 31.131,61.9 42.281,50.75 45.996,50.75 53.955,42.791 53.955,36.17 54.161,35.965 54.161,33.406 53.927,33.173 53.927,31.332 51.802,29.207 51.802,24.789 51.812,24.78 51.812,24.638 v1(51.85,24.6)
I2S.SDO_1: I2S_SDO.X J1.62 U2.39 | length 71.4
  Top Layer w0.19: J1.62@50.41,18.685 50.41,19.393 50.868,19.851 50.868,23.772 51.2,24.105 v1(51.2,24.6)
  Top Layer w0.2: v1(21.855,66.58) 21.855,67.182 22.424,67.75 U2.39@23.35,67.75
  Bottom Layer w0.2: I2S_SDO.X@21,68 21.485,67.515 21.485,66.95 21.894,66.541 21.894,66.225 26.569,61.55 30.945,61.55 31.424,61.072 42.095,50.4 43.732,50.4 45.851,50.4 52.667,43.584 52.667,43.548 53.605,42.609 53.605,36.025 53.811,35.82 53.811,33.551 53.577,33.318 53.577,31.477 51.426,29.326 51.426,24.826 v1(51.2,24.6)
I2S.WS_1: I2S_WS.X J1.58 U2.40 | length 73
  Top Layer w0.2: v1(22.567,67.257) 22.574,67.25 U2.40@23.35,67.25 ; J1.58@51.21,18.685 51.21,19.224 51.553,19.567 51.553,23.318 52.5,24.266 v1(52.5,24.6)
  Bottom Layer w0.2: I2S_WS.X@21,70 21.199,70 21.517,69.682 22.134,69.682 22.425,69.391 22.425,68.922 22.219,68.716 22.219,67.616 22.567,67.268 22.567,67.203 22.673,67.097 22.673,66.532 25.855,63.35 30.176,63.35 42.426,51.1 46.141,51.1 54.305,42.936 54.305,36.315 54.511,36.11 54.511,33.261 54.277,33.028 54.277,31.187 52.168,29.078 52.168,24.99 52.4,24.757 52.4,24.754 52.5,24.654 v1(52.5,24.6)
ILIM_bq_12: R72.1 U11.10 | length 1.6
  Top Layer w0.2: U11.10@92.35,38.025 92.35,37.3 92.616,37.034 R72.1@92.616,36.575
JTAG.R\E\S\E\T\_1: CN1.10 J1.73 JTAG_RST.X U15.25 | length 122.9
  Top Layer w0.2: v1(3.412,29.327) 3.45,29.289 3.711,29.289 4.225,28.775 4.225,26.098 v1(5.027,25.296) ; CN1.10@5.478,18.545 v1(6.978,18.545) ; v1(12.582,58.004) 15.205,58.004 15.639,58.438 U15.25@15.639,59.688 ; J1.73@48.01,15.605 48,15.595 48,14.808 48.308,14.5 48.308,7.61 49.518,6.4 v1(49.7,6.4)
  Bottom Layer w0.2: JTAG_RST.X@2,27 3.553,28.553 3.553,29.328 v1@3.506,29.375 ; v1(3.412,29.327) v1@3.482,29.398 ; v1@3.505,29.375 2.755,30.125 2.755,31.7 4.25,33.195 4.25,36.15 1.6,38.8 1.6,43.266 5.134,46.8 9.208,46.8 9.562,47.153 9.562,47.675 9.99,48.102 11.397,48.102 12.505,49.211 12.505,57.787 12.543,57.824 12.543,57.965 v1(12.582,58.004) ; v1(5.027,25.296) 6.819,23.504 6.819,18.758 6.978,18.599 6.978,15.047 7.675,14.35 12.175,14.35 14.375,12.15 14.375,8.325 14.825,7.875 24.882,7.875 26.907,5.85 40.95,5.85 42.029,6.929 49.09,6.929 49.619,6.4 v1(49.7,6.4)
JTAG.TCK/SCK_1: CN1.4 J1.77 JTAG_SCK.X U15.39 | length 112.2
  Top Layer w0.2: v1(0.636,26.663) 0.636,25.356 1.081,24.911 2.799,24.911 3.435,24.275 3.435,23.048 v1(4.125,22.358) 5.475,22.358 CN1.4@5.478,22.355 ; v1(8.649,53.853) 8.649,54.347 9.139,54.838 U15.39@10.289,54.838 ; J1.77@47.21,15.605 47.21,14.398 47.508,14.1 47.508,6.692 v1(48.8,5.4)
  Bottom Layer w0.2: v1(0.636,26.663) 0.636,43.436 4.842,47.642 4.842,50.046 v1(8.649,53.853) ; JTAG_SCK.X@2,23 2.642,22.358 v1(4.125,22.358) 5.378,21.105 5.378,15.645 7.398,13.625 11.898,13.625 13.55,11.973 13.55,8.16 14.56,7.15 24.539,7.15 26.643,5.046 41.172,5.046 42.149,6.023 48.177,6.023 v1(48.8,5.4)
JTAG.TDI_1: CN1.8 J1.78 JTAG_TDI.X U15.11 | length 140.8
  Top Layer w0.15: v1(14.6,50.964) 15.095,50.964 15.1,50.97 17.33,50.97 v1(17.335,50.975)
  Top Layer w0.2: v1(3.535,19.814) 5.477,19.814 CN1.8@5.478,19.815 5.485,19.822 v1(7.43,19.822) ; U15.11@21.489,55.338 22.719,55.338 22.839,55.218 v1(22.893,55.218) ; J1.78@47.21,18.685 47.21,17.51 46.4,16.7 46.4,14.008 46.708,13.7 46.708,5.492 v1(47.8,4.4)
  Bottom Layer w0.15: v1(17.335,50.975) 17.335,50.999 19.194,52.858 19.194,53.274 19.995,54.075 21.75,54.075 v1(22.893,55.218)
  Bottom Layer w0.2: JTAG_TDI.X@2,29 1.237,28.237 1.237,26.344 0.441,25.548 0.441,21.198 1.615,20.024 3.322,20.024 3.532,19.814 v1(3.535,19.814) 3.535,12.608 7.143,9 9.473,9 12.046,6.427 24.13,6.427 26.327,4.23 41.346,4.23 42.261,5.145 47.045,5.145 47.79,4.4 v1(47.8,4.4) ; v1(7.43,19.822) 7.43,20.534 7.35,20.614 7.35,27.405 8.35,28.405 8.35,30.175 5.4,33.125 5.4,36.625 2.65,39.375 2.65,42.788 5.612,45.75 11.285,45.75 14.6,49.065 v1(14.6,50.964)
JTAG.TDO/SWO_1: CN1.6 J1.79 JTAG_SWO.X R80.2 U15.10 | length 127.9
  Top Layer w0.2: v1(3.86,20.526) 3.898,20.564 3.898,20.851 4.132,21.085 CN1.6@5.478,21.085 ; v1(11.498,47.209) 12.969,45.738 R80.2@14.194,45.738 ; v1(13.371,54.838) U15.10@21.489,54.838 ; J1.79@46.81,15.605 46.81,14.198 47.108,13.9 47.108,6.092 v1(48.3,4.9)
  Bottom Layer w0.2: v1(13.371,54.838) 12.855,54.322 12.855,48.566 10.739,46.45 5.279,46.45 1.95,43.121 1.95,38.945 4.6,36.295 4.6,33.05 3.15,31.6 3.15,30.32 4.275,29.195 4.275,27.564 2.961,26.25 2.189,26.25 1.25,25.311 1.25,21.75 JTAG_SWO.X@2,21 2.216,21 2.691,20.526 v1(3.86,20.526) 5.028,19.357 5.028,15.472 7.235,13.265 7.91,13.265 8.95,12.225 8.95,10.1 12.273,6.777 24.416,6.777 26.498,4.696 41.317,4.696 42.116,5.495 47.705,5.495 v1(48.3,4.9)
JTAG.TMS/SWD_1: CN1.2 J1.75 JTAG_SWD.X U15.8 | length 123.7
  Top Layer w0.2: v1(4.125,23.628) 5.475,23.628 CN1.2@5.478,23.625 ; v1(13.305,54.038) 13.344,54 13.743,54 13.906,53.838 U15.8@21.489,53.838 ; J1.75@47.61,15.605 47.61,14.598 47.908,14.3 47.908,7.238 v1(49.246,5.9)
  Bottom Layer w0.2: JTAG_SWD.X@2,25 3.15,25 3.198,24.951 3.978,24.951 ; v1(13.305,54.038) 13.267,54 13.267,53.858 13.221,53.812 13.221,48.18 11.14,46.1 5.424,46.1 2.3,42.976 2.3,39.09 5,36.39 5,33.03 5.455,32.575 8,30.03 8,28.55 6.38,26.93 5.957,26.93 3.978,24.951 ; v1(49.246,5.9) 48.774,6.373 41.968,6.373 41.07,5.475 26.787,5.475 24.737,7.525 14.68,7.525 13.975,8.23 13.975,12.043 12.043,13.975 7.55,13.975 5.825,15.7 5.825,21.927 4.087,23.666 4.087,23.72 3.978,23.829 3.978,24.39 3.978,24.951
